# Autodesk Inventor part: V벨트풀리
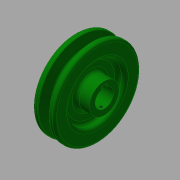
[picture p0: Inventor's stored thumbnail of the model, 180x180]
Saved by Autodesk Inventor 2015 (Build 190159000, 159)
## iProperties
Created: 2015-11
Part Number: V벨트풀리
Material: 강철, 탄소
Document SubType Name: Modeling
Designer: mduedu
Density: 1 g/cm^3
Appearance: 진녹색
Author: mduedu
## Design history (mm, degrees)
sketch "스케치1"
  geometry: L1 (-9.5, 0)-(9.5, 0); L2 (0, 0)-(0, 37.7); L3 (-4.825, 37.7)-(-9.5, 37.7); L4 (-9.5, 37.7)-(-9.5, 0); L5 (0, 28.7)-(-2.074, 28.7); L6 (-2.074, 28.7)-(-4.825, 37.7); L7 (4.825, 37.7)-(9.5, 37.7); L8 (9.5, 37.7)-(9.5, 0); L9 (0, 28.7)-(2.074, 28.7); L10 (2.074, 28.7)-(4.825, 37.7); L11 (-9.5, 35)-(9.5, 35); 3 further points
  constraints: 22 end point, 7 point on line, 4 perpendicular, 3 symmetric about line, 1 coincident, 1 horizontal, 1 horizontal alignment, 1 midpoint, 1 vertical
  dimensions: "d0" = 19 distance of L1.start L1.end; "d2" = 75.4 diameter of L2.end L1 (derived); "d3" = 34 deg angle of L10 L6; "d4" = 6.3 distance between parallel lines of L11 L9; "d5" = 2.7 distance between parallel lines of L7 L11; "d6" = 8 distance of point (4, 35) point (-4, 35); "d7" = 70 diameter of L11 L1
revolve "회전1" sketch "스케치1" stored, may be unused: angle "d8" = 90 deg
sketch "스케치2"
  geometry: C1 r 24 at (0, 0); C2 r 13 at (0, 0); 1 further point
  constraints: 2 centre point, 2 coincident
  dimensions: "d9" = 48 diameter of C1; "d10" = 26 diameter of C2
extrude "돌출1" cut sketch "스케치2" distance "d11" = 6; taper "d12" = 0 deg
extrude "돌출3" join sketch "스케치2" distance "d37" = 6; taper "d38" = 0 deg
fillet "모깎기1" dims "d13" = 3
fillet "모깎기2" dims "d14" = 3
fillet "모깎기3" dims "d15" = 1, "d16" = 0.5, "d17" = 2
hole "구멍1" diameter "d20" = 16; stored, may be unused: countersink angle "d24" = 90 deg, drill point angle "d26" = 118 deg; dims "d21" = 6, "d22" = 4, "d23" = 2, "d25" = 8, "d53" = 10, "d54" = 10
sketch "스케치3"
  geometry: L1 (-2.5, 0)-(2.5, 0); L2 (2.5, 0)-(2.5, 10.3); L3 (2.5, 10.3)-(-2.5, 10.3); L4 (-2.5, 10.3)-(-2.5, 0); 2 further points
  constraints: 8 end point, 2 parallel, 1 coincident, 1 horizontal, 1 midpoint, 1 perpendicular
  dimensions: "d27" = 5 distance of L2.end L3.end; "d29" = 10.3 distance of L3.end L1.start
extrude "돌출2" cut sketch "스케치3" stored distance "d30" = 6; taper "d31" = 0 deg
node "작업 평면1"
sketch "스케치4"
  geometry: L1 (19, -27)-(19, 27) reference; 2 further points
  constraints: 1 horizontal alignment
  dimensions: "d52" = 22 distance from line of L1 point (-3, 0)
hole "구멍2" sketch "스케치4" at (-3, 0) diameter "d42" = 2.459; stored, may be unused: countersink angle "d46" = 90 deg, drill point angle "d48" = 118 deg; dims "d43" = 6, "d44" = 4, "d45" = 2, "d47" = 8
node "솔리드1"
mirror "대칭1"
